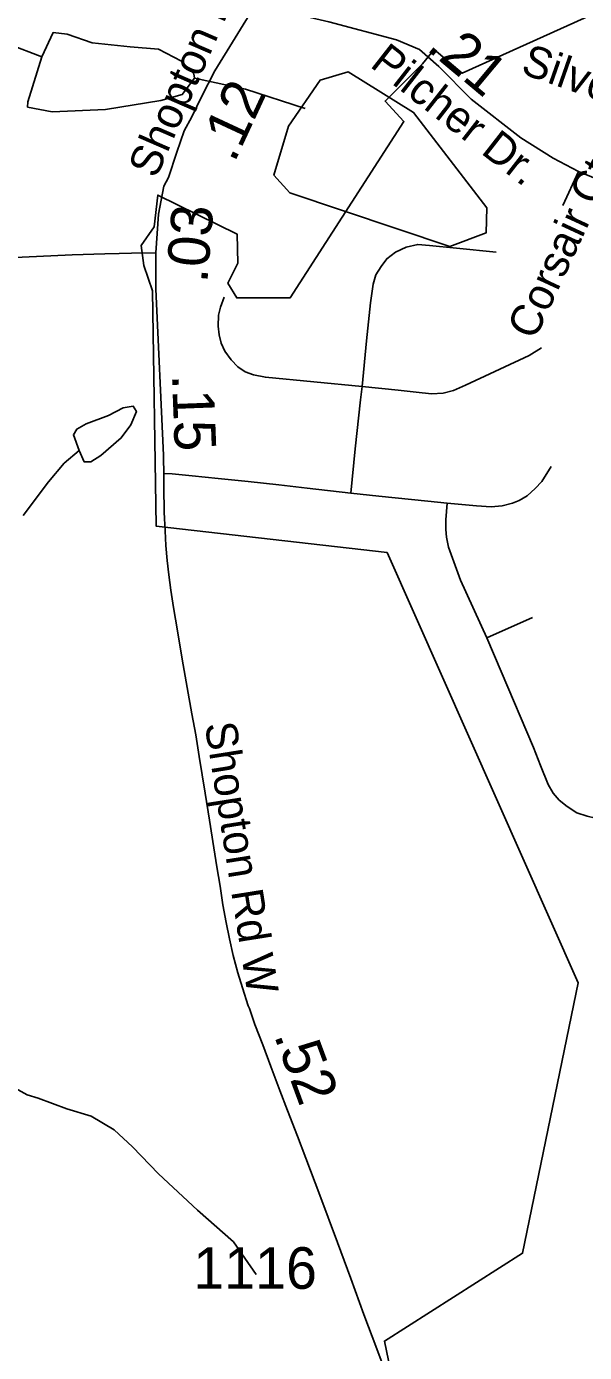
# Model space of a CAD drawing. Extents: x 1383679 to 1536984, y 460658 to 651027.
# Drawn here: x 1398965 to 1400643, y 496032 to 500019 of the extents above; entities that cross this region are included whole.
import ezdxf

# ---------------------------------------------------------------- set-up
doc = ezdxf.new("R2010")
doc.units = 0
for name, color, linetype in [('Default', 7, 'Continuous'), ('Exist Boundary Political City Limit New', 7, 'Continuous'), ('Exist Hydrographic Misc Water Feature', 7, 'Continuous'), ('Exist Road Non-System Type 51', 7, 'Continuous'), ('Exist Road Non-System Type 51 Label', 7, 'Continuous'), ('Exist Road Secondary Mileage Hundredths English Label', 7, 'Continuous'), ('Exist Road Secondary Type 51 Attributed', 7, 'Continuous'), ('Exist Road Secondary Type 51 Label', 7, 'Continuous'), ('Exist Road Secondary Type 51 Number Label', 7, 'Continuous'), ('Map Preparation Boundary City Limit Buffer Line', 7, 'Continuous')]:
    doc.layers.add(name, color=color, linetype=linetype)

msp = doc.modelspace()

# ---------------------------------------------------------------- linework, layer by layer
at = {"layer": 'Default'}
msp.add_lwpolyline([(1400162.1, 495483.2), (1400041, 496066.2), (1400456.8, 496330.5), (1400623.6, 497143.7), (1400049.2, 498437.7), (1399354.4, 498516.8), (1399343.2, 499223.8), (1399317.8, 499300.4), (1399309.1, 499360.8), (1399348.4, 499416.5), (1399359.6, 499511.9), (1399598.5, 499394.2), (1399599.8, 499307.5), (1399569.8, 499247.6), (1399596.8, 499202.9), (1399758, 499203.1), (1400099.9, 499732.8), (1400043.2, 499794.7), (1400155.5, 499906.2), (1400191.2, 499949.3), (1400275.4, 499878.3), (1402231.4, 500761.4)], dxfattribs=at)
at = {"layer": 'Exist Boundary Political City Limit New'}
msp.add_lwpolyline([(1400162.1, 495483.2), (1400041, 496066.2), (1400456.8, 496330.5), (1400623.6, 497143.7), (1400049.2, 498437.7), (1399354.4, 498516.8), (1399343.2, 499223.8), (1399317.8, 499300.4), (1399309.1, 499360.8), (1399348.4, 499416.5), (1399359.6, 499511.9), (1399598.5, 499394.2), (1399599.8, 499307.5), (1399569.8, 499247.6), (1399596.8, 499202.9), (1399758, 499203.1), (1400099.9, 499732.8), (1400043.2, 499794.7), (1400155.5, 499906.2), (1400191.2, 499949.3), (1400275.4, 499878.3), (1402231.4, 500761.4)], dxfattribs=at)
at = {"layer": 'Exist Hydrographic Misc Water Feature'}
for points in [[(1399011.2, 499927.3), (1399044.8, 500000.5), (1399086.7, 499995.6), (1399162.1, 499970.2), (1399276, 499958.1), (1399361.8, 499950.7), (1399431.3, 499914.8), (1399460.6, 499883.9), (1399468.4, 499876.3), (1399470.1, 499864)], [(1398912, 499965.4), (1399011.2, 499927.3)], [(1399470.1, 499864), (1399433.1, 499814.7), (1399368.7, 499796.3), (1399202.1, 499769.2), (1399041.9, 499762.6), (1398968, 499776.4), (1398968.5, 499792), (1399011.2, 499927.3)], [(1399470.1, 499864), (1399623.5, 499830.5), (1399802.4, 499772.7)], [(1400237.8, 499357.8), (1400346.8, 499398.3), (1400348.7, 499473.8), (1400128.8, 499760.5), (1399931.8, 499882.6), (1399847.8, 499858), (1399752.8, 499718.8), (1399708.8, 499571.9), (1399756.8, 499518.4), (1400237.8, 499357.8)], [(1399122.7, 498744.2), (1399105.6, 498791.4), (1399116.1, 498808.4), (1399144.4, 498824.3), (1399210.9, 498849.2), (1399255.4, 498872.1), (1399285.6, 498877.2), (1399295.2, 498861.4), (1399278.4, 498821.5), (1399249.6, 498781.9), (1399188.5, 498729), (1399158, 498709.9), (1399138, 498710.3), (1399122.7, 498744.2)], [(1399122.7, 498744.2), (1399078, 498705.8), (1399030.7, 498650.1), (1398954.6, 498548.2)], [(1399655.5, 496266), (1399587.5, 496364.2), (1399479.4, 496459.9), (1399361.6, 496568.9), (1399283.2, 496650.1), (1399228.3, 496701.3), (1399159.2, 496742.9), (1399085.5, 496764.1), (1399000.2, 496796.1), (1398966.4, 496806.7), (1398901.2, 496842.5)]]:
    msp.add_lwpolyline(points, dxfattribs=at)
at = {"layer": 'Exist Road Non-System Type 51'}
msp.add_line((1400486.2, 498241.8), (1400349.4, 498180.9), dxfattribs=at)
for points in [[(1400625.2, 499582.8), (1400578, 499481.1)], [(1400376.8, 499340.3), (1400258, 499352.2), (1400177.1, 499360.9), (1400141.6, 499363.8), (1400106.9, 499355.2), (1400074.1, 499340.7), (1400048.1, 499320.5), (1400030.9, 499297.4), (1400015.4, 499272.3), (1400006.8, 499244.4), (1399999.5, 499187.9), (1399987.2, 499074.1), (1399974.1, 498936.8)], [(1399974.1, 498936.8), (1399683.4, 498964.3), (1399647.8, 498971.1), (1399622.8, 498980.8), (1399600.6, 498995.2), (1399579.9, 499016.7), (1399561.1, 499043), (1399550.6, 499066.4), (1399543.9, 499091.4), (1399540.9, 499118.3), (1399541.9, 499151.1), (1399548.6, 499175.2), (1399559.2, 499204.8)], [(1400513.1, 499052.4), (1400476.5, 499029.8), (1400284.6, 498940.5), (1400248.9, 498924.5), (1400217.8, 498916), (1400183, 498914.2), (1400136.9, 498919.8), (1400082.4, 498925.4), (1399974.1, 498936.8)], [(1399974.1, 498936.8), (1399969.4, 498896.2), (1399953.4, 498748.6), (1399940, 498615.6)], [(1400542.8, 498695.8), (1400515, 498651.2), (1400494.1, 498629.4), (1400470.4, 498607.7), (1400446.6, 498593.8), (1400426.8, 498585.8), (1400395, 498577.9), (1400362.4, 498574.9), (1400317.8, 498577.9), (1400229.5, 498585.8)], [(1399940, 498615.6), (1399809.1, 498630.4), (1399723.9, 498640.4), (1399631.6, 498650.8), (1399541.4, 498660.2), (1399463.2, 498667.7), (1399403.1, 498674.2), (1399377, 498674.4)], [(1400229.5, 498585.8), (1400172, 498591.8), (1400024.2, 498606.7), (1399940, 498615.6)], [(1400229.5, 498585.8), (1400225.5, 498535.2), (1400225.5, 498506.5), (1400227.5, 498483.8), (1400233.4, 498453), (1400270.4, 498354.4), (1400349.4, 498180.9)], [(1400349.4, 498180.9), (1400391.9, 498079.7), (1400489.6, 497851.1), (1400510.1, 497796.4), (1400534.1, 497740.1), (1400548.6, 497714), (1400566.4, 497693.1), (1400590.4, 497673.2), (1400619.6, 497654.5), (1400650.9, 497644.1), (1400676, 497638.8), (1400719.9, 497638.8), (1401001.6, 497647.2), (1401114.2, 497651.4), (1401171.6, 497654.5), (1401213.1, 497662), (1401247.9, 497671.4), (1401334.4, 497714.7)]]:
    msp.add_lwpolyline(points, dxfattribs=at)
at = {"layer": 'Exist Road Secondary Type 51 Attributed'}
for points in [[(1399652.9, 500083.8), (1399531.2, 499886.1), (1399491.8, 499809.6), (1399462.4, 499746.9), (1399438.8, 499704.8), (1399417.1, 499640.9), (1399391.7, 499564.6), (1399377.4, 499538.7), (1399361.6, 499454.6), (1399353.7, 499338)], [(1399652.9, 500083.8), (1399874.2, 500033), (1400077.4, 499978.6), (1400146.3, 499949.5), (1400204.4, 499898.7), (1400302.3, 499800.6), (1400451.1, 499684.5), (1400549, 499622.7), (1400625.2, 499582.8)], [(1400625.2, 499582.8), (1400810.2, 499506.6), (1400955.3, 499452.1), (1401053.3, 499412.2)], [(1399353.7, 499338), (1399280.7, 499337.8), (1399243.1, 499336.5), (1399199.8, 499335.2), (1399102.4, 499332.3), (1398908, 499323.6)], [(1399353.7, 499338), (1399353.7, 499229), (1399376.3, 498730.1), (1399377.2, 498667.2), (1399377.6, 498633.9), (1399379.1, 498558.3), (1399381.3, 498502.4), (1399383.8, 498458.3), (1399387.6, 498413.1), (1399392.7, 498370.1), (1399399.1, 498323.8), (1399407, 498271.9), (1399418.8, 498201.8), (1399433.2, 498116.5), (1399447.8, 498031.8), (1399462.3, 497951.8), (1399473.6, 497889.3), (1399484, 497824.4), (1399493.3, 497768.3), (1399501.9, 497714), (1399515.2, 497632.6), (1399528.1, 497549.3), (1399537, 497491.9), (1399546.9, 497434.5), (1399555.3, 497378.2), (1399565.3, 497324.3), (1399574.8, 497275.8), (1399586.1, 497225.2), (1399600.1, 497173.4), (1399613.9, 497128.3), (1399631.8, 497074.7), (1399634.9, 497066), (1399651.8, 497018.2), (1399675.3, 496956.8), (1399699.7, 496892.1), (1399726.5, 496819.6), (1399750, 496759.5), (1399779.4, 496682.8), (1399804.5, 496615.9), (1399847.1, 496504.6), (1399900.1, 496362.4), (1399939.8, 496254.2), (1399979.4, 496146.4), (1400018.3, 496043), (1400062.6, 495925)]]:
    msp.add_lwpolyline(points, dxfattribs=at)
at = {"layer": 'Map Preparation Boundary City Limit Buffer Line'}
msp.add_lwpolyline([(1400162.1, 495483.2), (1400041, 496066.2), (1400456.8, 496330.5), (1400623.6, 497143.7), (1400049.2, 498437.7), (1399354.4, 498516.8), (1399343.2, 499223.8), (1399317.8, 499300.4), (1399309.1, 499360.8), (1399348.4, 499416.5), (1399359.6, 499511.9), (1399598.5, 499394.2), (1399599.8, 499307.5), (1399569.8, 499247.6), (1399596.8, 499202.9), (1399758, 499203.1), (1400099.9, 499732.8), (1400043.2, 499794.7), (1400155.5, 499906.2), (1400191.2, 499949.3), (1400275.4, 499878.3), (1402231.4, 500761.4)], dxfattribs=at)
msp.add_lwpolyline([(1400162.1, 495483.2), (1400041, 496066.2), (1400456.8, 496330.5), (1400623.6, 497143.7), (1400049.2, 498437.7), (1399354.4, 498516.8), (1399343.2, 499223.8), (1399317.8, 499300.4), (1399309.1, 499360.8), (1399348.4, 499416.5), (1399359.6, 499511.9), (1399598.5, 499394.2), (1399599.8, 499307.5), (1399569.8, 499247.6), (1399596.8, 499202.9), (1399758, 499203.1), (1400099.9, 499732.8), (1400043.2, 499794.7), (1400155.5, 499906.2), (1400191.2, 499949.3), (1400275.4, 499878.3), (1402231.4, 500761.4)], dxfattribs=at)

# ---------------------------------------------------------------- texts
at = {"layer": 'Exist Road Non-System Type 51 Label'}
for s, rotation, p in [('Silver Dart Pl.', 340.7548, (1400447.6, 499879)), ('Corsair Ct.', 65.1129, (1400493.2, 499072.9))]:
    msp.add_text(s, height=95, rotation=rotation, dxfattribs=at).set_placement(p)
at = {"layer": 'Exist Road Secondary Mileage Hundredths English Label'}
for s, rotation, p in [('.21', 320.0953, (1400164.2, 499951)), ('.12', 65.0892, (1399589.6, 499606.6)), ('.03', 85.2401, (1399508.2, 499245.7)), ('.15', 272.1459, (1399402.1, 498972.1)), ('.52', 290.2754, (1399708, 496985.7))]:
    msp.add_text(s, height=125, rotation=rotation, dxfattribs=at).set_placement(p)
at = {"layer": 'Exist Road Secondary Type 51 Label'}
for s, rotation, p in [('Shopton Rd West', 66.5498, (1399354.6, 499559)), ('Pilcher Dr.', 322.0059, (1399994.5, 499900)), ('Shopton Rd W', 279.0122, (1399500.3, 497920.9))]:
    msp.add_text(s, height=95, rotation=rotation, dxfattribs=at).set_placement(p)
at = {"layer": 'Exist Road Secondary Type 51 Number Label'}
msp.add_text('1116', height=125, dxfattribs=at).set_placement((1399466.3, 496223.4))

doc.saveas('drawing.dxf')
